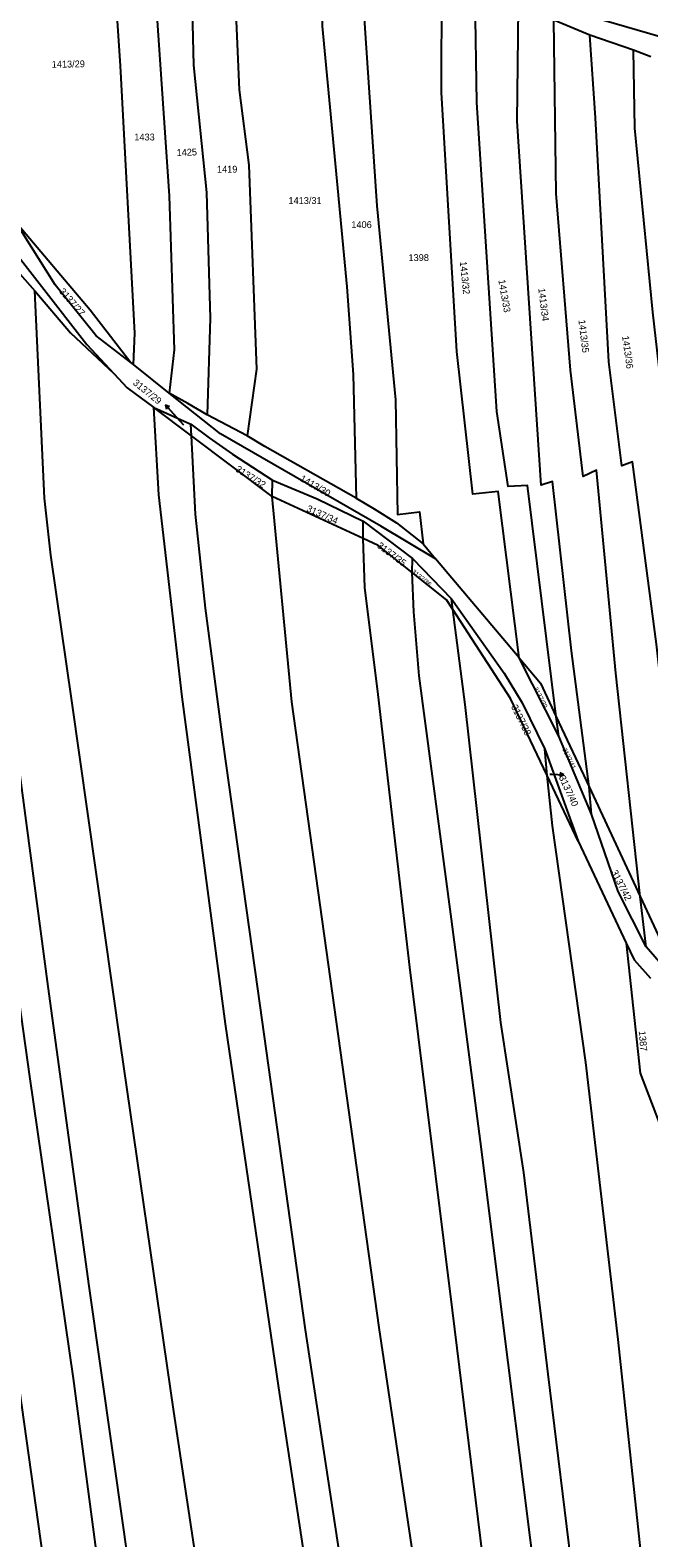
# Model space of a CAD drawing. Extents: x -776734 to -748832, y -1118122 to -976986.
# Drawn here: x -752331.8 to -752178.5, y -1116225.4 to -1115852 of the extents above; entities that cross this region are included whole.
import ezdxf

# ---------------------------------------------------------------- set-up
doc = ezdxf.new("R2010")
doc.units = 0
for name, color, linetype in [('KM_Hranice parcel', 7, 'Continuous'), ('KM_Parcelní čísla', 7, 'Continuous'), ('KM_Pop  PČ popisy', 7, 'Continuous')]:
    doc.layers.add(name, color=color, linetype=linetype)

msp = doc.modelspace()

# ---------------------------------------------------------------- linework, layer by layer
at = {"layer": 'KM_Hranice parcel'}
for p, q in [((-752193.05, -1115853.24), (-752202.04, -1115849.49)), ((-752182.25, -1115856.92), (-752193.05, -1115853.24)), ((-752177.95, -1115858.57), (-752182.25, -1115856.92)), ((-752306.24, -1115934.8), (-752306.87, -1115934.3)), ((-752297.34, -1115941.88), (-752306.24, -1115934.8)), ((-752291.83, -1115952.45), (-752301.16, -1115945.46)), ((-752301.16, -1115945.46), (-752291.97, -1115949.58)), ((-752278.04, -1115952.41), (-752287.99, -1115947.27)), ((-752291.83, -1115952.45), (-752291.97, -1115949.58)), ((-752271.82, -1115967.45), (-752291.83, -1115952.45)), ((-752271.82, -1115967.45), (-752271.74, -1115963.41)), ((-752249.3, -1115977.86), (-752271.82, -1115967.45)), ((-752249.3, -1115977.86), (-752249.28, -1115973.58)), ((-752249.28, -1115973.58), (-752237.01, -1115982.84)), ((-752234.43, -1115979.17), (-752231.31, -1115982.93)), ((-752237.12, -1115986.31), (-752237.01, -1115982.84)), ((-752237.01, -1115982.84), (-752227.38, -1115992.8)), ((-752210.61, -1116007.41), (-752231.31, -1115982.93)), ((-752227.03, -1115995.49), (-752227.38, -1115992.8)), ((-752200.8, -1116026.82), (-752210.61, -1116007.41)), ((-752200.8, -1116026.82), (-752201.4, -1116022.04)), ((-752201.4, -1116022.04), (-752193.29, -1116039.41)), ((-752203.7, -1116036.61), (-752204.24, -1116030.02)), ((-752204.24, -1116030.02), (-752196.02, -1116052.85)), ((-752192.66, -1116046.11), (-752200.8, -1116026.82)), ((-752196.02, -1116052.85), (-752203.7, -1116036.61)), ((-752192.66, -1116046.11), (-752193.29, -1116039.41)), ((-752193.29, -1116039.41), (-752180.64, -1116066.51)), ((-752196.02, -1116052.85), (-752184.07, -1116078.11)), ((-752179.16, -1116078.98), (-752180.64, -1116066.51)), ((-752168.72, -1116091.06), (-752179.16, -1116078.98))]:
    msp.add_line(p, q, dxfattribs=at)
for points in [[(-752306.24, -1115934.8), (-752305.87, -1115927.03), (-752309.42, -1115860.77), (-752312.07, -1115821.19)], [(-752302.22, -1115821.88), (-752297.34, -1115893.04), (-752296.1, -1115931.12), (-752297.34, -1115941.88)], [(-752292.24, -1115823.25), (-752291.33, -1115860.63), (-752288.15, -1115892.16), (-752287.23, -1115923.29), (-752287.99, -1115947.27)], [(-752281.41, -1115824.93), (-752281.32, -1115836.31), (-752280, -1115866.75), (-752277.64, -1115885.39), (-752275.73, -1115935.9), (-752278.04, -1115952.41)], [(-752259.2, -1115829.32), (-752259.41, -1115851.01), (-752253.35, -1115915.53), (-752251.73, -1115937.24), (-752250.98, -1115967.91)], [(-752244.75, -1115830.41), (-752239.78, -1115832.43), (-752214.29, -1115840.49), (-752189.58, -1115849.47), (-752164.25, -1115856.85), (-752141.87, -1115862.01), (-752121.83, -1115861.15), (-752096.62, -1115861.4), (-752033.58, -1115879.94)], [(-752249.81, -1115833.11), (-752249.15, -1115847.87), (-752245.93, -1115895.47), (-752241.24, -1115943.57), (-752240.73, -1115971.92), (-752235.35, -1115971.26), (-752234.43, -1115979.17)], [(-752210.61, -1116007.41), (-752215.79, -1115966.23), (-752222.07, -1115966.89), (-752226.09, -1115931.56), (-752229.88, -1115867.43), (-752229.78, -1115840.79)], [(-752201.4, -1116022.04), (-752208.57, -1115964.74), (-752213.36, -1115964.99), (-752216.13, -1115946.38), (-752221.14, -1115869.9), (-752221.49, -1115843.91)], [(-752193.29, -1116039.41), (-752197.63, -1116005.72), (-752202.38, -1115963.75), (-752205.19, -1115964.64), (-752211.14, -1115874.5), (-752210.8, -1115846.44)], [(-752180.64, -1116066.51), (-752186.67, -1116011.19), (-752191.41, -1115960.97), (-752194.7, -1115962.49), (-752197.87, -1115936.22), (-752201.41, -1115892.41), (-752202.04, -1115849.49)], [(-752168.74, -1116086.25), (-752168.78, -1116073.92), (-752176.6, -1116004.07), (-752182.5, -1115958.91), (-752185.13, -1115959.87), (-752188.35, -1115934.16), (-752191.68, -1115873.68), (-752193.05, -1115853.24)], [(-752156.62, -1116102.03), (-752158.4, -1116073.41), (-752161.79, -1116037.58), (-752164.91, -1116014.77), (-752172.39, -1115954.41), (-752173.72, -1115954.45), (-752177.46, -1115921.84), (-752181.92, -1115876.22), (-752182.25, -1115856.92)], [(-752449.01, -1115864.29), (-752432.91, -1115869.64), (-752371.1, -1115881.13), (-752353.98, -1115888.12), (-752339.74, -1115901.65), (-752317.75, -1115929.82), (-752311.07, -1115936.98)], [(-752370.73, -1115884.02), (-752370.45, -1115905.57), (-752368.96, -1115927.51), (-752363.46, -1115977.39), (-752357.56, -1116031.42), (-752347.92, -1116088.84), (-752337.37, -1116168.34), (-752327.05, -1116242.07), (-752317.09, -1116312.95), (-752310.6, -1116362.2), (-752305.19, -1116410.26), (-752301.82, -1116473.3)], [(-752279.9, -1116504.83), (-752287.09, -1116434.38), (-752290.06, -1116410.92), (-752293.31, -1116388.89), (-752306.19, -1116294.65), (-752313.53, -1116243.23), (-752321.13, -1116185.88), (-752331.92, -1116111.14), (-752348.44, -1115993.45), (-752352.58, -1115953.97), (-752354.87, -1115921.17), (-752354.86, -1115892.88)], [(-752306.87, -1115934.3), (-752315.5, -1115927.7), (-752325.67, -1115915.01), (-752335.57, -1115899.3)], [(-752335.57, -1115899.3), (-752316.95, -1115921.22), (-752306.87, -1115934.3)], [(-752253.69, -1116634.86), (-752258.04, -1116598.69), (-752262.83, -1116565.13), (-752271.97, -1116504.15), (-752278.44, -1116440.59), (-752283.01, -1116406.81), (-752290.04, -1116352.06), (-752297.06, -1116306.23), (-752308.65, -1116223.4), (-752317.23, -1116163.08), (-752327.37, -1116088.83), (-752343.3, -1115969.19), (-752347.04, -1115908.82), (-752346.76, -1115899.51)], [(-752346.76, -1115899.51), (-752344.35, -1115901.09), (-752338.13, -1115908.12), (-752330.65, -1115916.55)], [(-752257.22, -1116509.03), (-752260.27, -1116471.82), (-752267.09, -1116404.2), (-752272.76, -1116363.94), (-752286.55, -1116258.27), (-752296.2, -1116194.12), (-752309.48, -1116102.95), (-752321.48, -1116018.12), (-752326.7, -1115981.99), (-752328.24, -1115967.89), (-752330.65, -1115916.55)], [(-752330.65, -1115916.55), (-752321.84, -1115926.92), (-752311.07, -1115936.98)], [(-752311.07, -1115936.98), (-752307.75, -1115940.53), (-752301.16, -1115945.46)], [(-752231.31, -1115982.93), (-752244.88, -1115974.86), (-752284.66, -1115951.96), (-752297.34, -1115941.88)], [(-752287.99, -1115947.27), (-752292.75, -1115944.42), (-752297.34, -1115941.88)], [(-752216.57, -1116627.23), (-752218.56, -1116588.51), (-752226.05, -1116526.07), (-752232.24, -1116489.5), (-752234.7, -1116457.99), (-752242.19, -1116393.36), (-752250.29, -1116330.27), (-752258.93, -1116262.05), (-752270.16, -1116188.19), (-752283.38, -1116098.07), (-752294.15, -1116017.06), (-752299.91, -1115967.04), (-752301.16, -1115945.46)], [(-752291.97, -1115949.58), (-752287.42, -1115952.95), (-752281.66, -1115957), (-752271.74, -1115963.41)], [(-752207.62, -1116625.39), (-752209.27, -1116586.63), (-752215.19, -1116540.76), (-752219.1, -1116510.78), (-752222.31, -1116494.65), (-752224.38, -1116479.9), (-752232.95, -1116394.72), (-752241.5, -1116326.55), (-752253.34, -1116241.12), (-752263.54, -1116173.84), (-752275.38, -1116089.41), (-752283.93, -1116028.88), (-752288.4, -1115995.17), (-752290.86, -1115971.86), (-752291.83, -1115952.45)], [(-752250.98, -1115967.91), (-752273.65, -1115955.07), (-752278.04, -1115952.41)], [(-752271.74, -1115963.41), (-752260.69, -1115968.01), (-752249.28, -1115973.58)], [(-752195.15, -1116492.48), (-752203.5, -1116492.29), (-752205.88, -1116477.18), (-752213.29, -1116399.52), (-752221.66, -1116337.23), (-752231.52, -1116265.79), (-752245.28, -1116173.25), (-752267, -1116018.36), (-752271.82, -1115967.45)], [(-752250.98, -1115967.91), (-752246.53, -1115970.5), (-752241.05, -1115974.03), (-752234.43, -1115979.17)], [(-752237.12, -1115986.31), (-752245.59, -1115979.58), (-752249.3, -1115977.86)], [(-752189.44, -1116480.52), (-752197.26, -1116401.99), (-752216.12, -1116258.36), (-752227.11, -1116168.97), (-752237.68, -1116084.01), (-752245.54, -1116016.54), (-752248.83, -1115990.02), (-752249.3, -1115977.86)], [(-752227.03, -1115995.49), (-752228.59, -1115993.09), (-752237.12, -1115986.31)], [(-752179, -1116493.47), (-752179.38, -1116475.12), (-752181.4, -1116446.62), (-752187.18, -1116393.7), (-752192.65, -1116355.44), (-752198.23, -1116309.87), (-752205.93, -1116241.1), (-752213.33, -1116181.94), (-752220.22, -1116127.25), (-752227.41, -1116072.15), (-752235.42, -1116011.89), (-752236.74, -1115996.07), (-752237.12, -1115986.31)], [(-752227.38, -1115992.8), (-752214.31, -1116011.23), (-752209.88, -1116018.61), (-752204.24, -1116030.02)], [(-752170.09, -1116496.27), (-752169.98, -1116474.66), (-752170.1, -1116467.17), (-752173.18, -1116429.39), (-752176.07, -1116403.57), (-752187.88, -1116318.02), (-752195.17, -1116252.22), (-752203.41, -1116184.83), (-752209.43, -1116134.87), (-752215.14, -1116097.77), (-752224.01, -1116018.96), (-752227.03, -1115995.49)], [(-752203.7, -1116036.61), (-752212.73, -1116017.52), (-752227.03, -1115995.49)], [(-752210.61, -1116007.41), (-752205.29, -1116013.7), (-752201.4, -1116022.04)], [(-752152.44, -1116507.96), (-752154.9, -1116486.41), (-752155.51, -1116424.06), (-752159.16, -1116397.81), (-752177.97, -1116252.03), (-752186.04, -1116176.29), (-752194.1, -1116107.65), (-752202.38, -1116049.01), (-752203.7, -1116036.61)], [(-752179.16, -1116078.98), (-752186.07, -1116065.33), (-752192.66, -1116046.11)], [(-752180.64, -1116066.51), (-752175.58, -1116077.34), (-752168.74, -1116086.25)], [(-752184.07, -1116078.11), (-752180.63, -1116110.3), (-752174.6, -1116126.07)], [(-752184.07, -1116078.11), (-752182.11, -1116082.25), (-752178.05, -1116086.74)]]:
    msp.add_lwpolyline(points, dxfattribs=at)
at = {"layer": 'KM_Pop  PČ popisy'}
for p, q in [((-752296.31, -1115947.02), (-752298.318, -1115944.79)), ((-752298.318, -1115944.79), (-752297.276, -1115945.199)), ((-752298.318, -1115944.79), (-752298.02, -1115945.869)), ((-752293.75, -1115949.82), (-752296.31, -1115947.02)), ((-752203.01, -1116036.24), (-752202.53, -1116036.27)), ((-752202.53, -1116036.27), (-752199.533, -1116036.427)), ((-752199.533, -1116036.427), (-752200.559, -1116036.875)), ((-752199.533, -1116036.427), (-752200.507, -1116035.875))]:
    msp.add_line(p, q, dxfattribs=at)

# ---------------------------------------------------------------- texts
at = {"layer": 'KM_Parcelní čísla'}
for s, height, rotation, p in [('1413/29', 1.7, 1, (-752326.475, -1115861.299)), ('1425', 1.7, 2, (-752295.51, -1115883.159)), ('1413/32', 1.7, 275.999997, (-752225.335, -1115909.308)), ('1413/33', 1.7, 280, (-752215.777, -1115913.907)), ('3137/27', 1.7, 311, (-752324.761, -1115916.777)), ('1413/34', 1.7, 277, (-752205.873, -1115915.973)), ('1413/35', 1.7, 277, (-752195.923, -1115923.803)), ('1413/36', 1.7, 278, (-752185.101, -1115927.788)), ('3137/29', 1.7, 321, (-752306.509, -1115939.604)), ('3137/32', 1.7, 328, (-752281.08, -1115961.14)), ('1413/30', 1.7, 329.999997, (-752265.125, -1115963.496)), ('3137/34', 1.7, 336, (-752263.485, -1115971.066)), ('3137/35', 1.7, 323, (-752245.981, -1115979.958)), ('3137/36', 1.14, 321, (-752237.344, -1115986.303)), ('3137/39', 1.14, 297, (-752207.097, -1116014.972)), ('3137/38', 1.7, 296, (-752212.653, -1116019.492)), ('3137/41', 1.14, 296, (-752199.953, -1116030.039)), ('3137/40', 1.7, 295, (-752200.823, -1116037.003)), ('3137/42', 1.7, 297, (-752187.857, -1116060.465)), ('1387', 1.7, 275, (-752180.976, -1116099.894))]:
    msp.add_text(s, height=height, rotation=rotation, dxfattribs=at).set_placement(p)
for s, p in [('1433', (-752306.01, -1115879.29)), ('1419', (-752285.53, -1115887.27)), ('1413/31', (-752267.8, -1115895.03)), ('1406', (-752252.21, -1115900.99)), ('1398', (-752238.04, -1115909.16))]:
    msp.add_text(s, height=1.7, dxfattribs=at).set_placement(p)

doc.saveas('drawing.dxf')
